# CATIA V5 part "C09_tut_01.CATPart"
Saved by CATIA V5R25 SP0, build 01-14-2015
Part number: Part1
Bounding box of the stored display mesh (mm): x -75 to 140, y -40 to 40, z 0 to 100
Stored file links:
  E:\ashutosh\Academics\Catia\CATIA V5-6R2013_partfiles\Tutorials_ver_2\C09_tut_01.CATPart
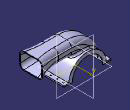
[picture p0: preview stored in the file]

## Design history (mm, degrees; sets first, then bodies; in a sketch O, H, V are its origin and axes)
Body1 (main body)
  Sketch1 on zx-plane, origin (0, 0, 0), H (-1, 0, 0), V (0, 0, 1)
    arc A1 centre (0, 0) radius 60 from (60, 0) to (-60, 0) ccw
    line L1 (-60, 0) -> (60, 0)
    point P1 (-60, 0)
    radius A1 = 60
    coincidence: P1 H
    horizontal: L1 H
  Pad1: profile Sketch1, direction (0, 1, 0), length 40, mirrored extent
  Sketch2 on zx-plane, origin (0, 0, 0), H (-1, 0, 0), V (0, 0, 1)
    point P1 (-82, 100)
    line L1 (-82, 100) -> (-40, 100)
    arc A1 centre (-40, 0) radius 100 from (-40, 100) to (60, 0) cw
    point P4 (60, 0)
    reference projected line E1 (-60, 0) -> (60, 0) from edge [face of Pad1 from Sketch1.L1 | end face of Pad1]
    reference projected point E2 (60, 0) from edge [face of Pad1 from Sketch1.A1 | face of Pad1 from Sketch1.L1]
    reference projected arc E3 centre (0, 0) radius 60 from (60, 0) to (-60, 0) ccw from edge [face of Pad1 from Sketch1.A1 | end face of Pad1]
    distance P1 E1 = 100
    distance P1 V = 82
    horizontal: L1 H
    tangency: A1 L1, A1 E3
    coincidence: P4 E2
  Plane1: type Normal, Curve Sketch2, RefPoint Sketch2.P1, Ratio 0
  Sketch3 on Plane1, origin (82, 0, 0), H (0, 1, 0), V (0, 0, 1)
    line L1 (-29, 100) -> (29, 100)
    line L2 (29, 100) -> (29, 58)
    line L3 (29, 58) -> (-29, 58)
    line L4 (-29, 58) -> (-29, 100)
    reference projected point E1 (0, 100) from Sketch2.P1
    distance L4 V = 29
    length L1 = 58
    length L2 = 42
    horizontal: L1 H, L3 H
    vertical: L2 V, L4 V
    coincidence: L1 E1
  Rib1: profile Sketch3, centre curve Sketch2
  Plane2: type Offset, RefPlane face of Rib1, Offset 58, reversed
  Sketch4 on Plane2, origin (140, 0, 0), H (0, -1, 0), V (0, 0, 1)
    line L1 (36.53, 100) -> (-36.47, 100)
    line L2 (-36.47, 100) -> (-36.47, 47)
    line L3 (-36.47, 47) -> (36.53, 47)
    line L4 (36.53, 47) -> (36.53, 100)
    reference projected line E1 (40, 0) -> (-40, 0) from edge [face of Rib1 | face of Pad1 from Sketch1.A1]
    distance L4 V = 36.53
    distance L1 E1 = 100
    length L2 = 53
    length L1 = 73
    horizontal: L1 H, L3 H
    vertical: L2 V, L4 V
  Loft1: solid, Sections ({boundary Boundary {extract ExtractElem face of Rib1}}; Sketch4), StartFace face of Rib1
  Fillet1: radius 15, on edge [face of Rib1 | face of Rib1] (x3); edge [face of Loft1 | face of Loft1]
  Shell1: ExtOffset 0, Face (face of Rib1; face of Loft1), IntOffset 2.5
  Fillet2: radius 5, on edge [face of Pad1 from Sketch1.A1 | face of Fillet1]
  Sketch5 on end face of Pad1, origin (0, 40, 0), H (-1, 0, 0), V (0, 0, 1)
    arc A1 centre (0, 0) radius 49 from (49, 0) to (-49, 0) ccw
    line L1 (-49, 0) -> (49, 0)
    point P1 (-49, 0)
    radius A1 = 49
    coincidence: P1 H
    horizontal: L1 H
  Pocket1: profile Sketch5, direction (0, -1, 0), through (limit type 6)
  Sketch6 on start face of Pad1, origin (0, -40, 0), H (1, 0, 0), V (0, 0, 1)
    circle A1 centre (0, 0) radius 15
    radius A1 = 15
  Pocket2: profile Sketch6, direction (0, 1, 0), through (limit type 6)
  Sketch7 on end face of Pad1, origin (0, 40, 0), H (-1, 0, 0), V (0, 0, 1)
    line L1 (60, 0) -> (75, 0)
    line L2 (75, 0) -> (75, 4)
    line L3 (75, 4) -> (59.8665, 4)
    point P4 (59.8665, 4)
    reference projected line E1 (-60, 0) -> (60, 0) from edge [face of Rib1 | end face of Pad1]
    reference intersected line E2 (60, 0) -> (-60, 0) from face of Rib1
    reference projected arc E3 centre (0, 0) radius 60 from (60, 0) to (-60, 0) ccw from edge [face of Pad1 from Sketch1.A1 | end face of Pad1]
    projected arc E4 centre (0, 0) radius 60 from (60, 0) to (-60, 0) ccw from edge [face of Pad1 from Sketch1.A1 | end face of Pad1]
    projected arc E5 centre (0, 0) radius 60 from (60, 0) to (59.8665, 4) ccw from edge [face of Pad1 from Sketch1.A1 | end face of Pad1]
    length L2 = 4
    distance L2 V = 75
    horizontal: L1 H, L3 H
    vertical: L2 V
    coincidence: L1 E1, L1 E2, P4 E3
  Pad2: profile Sketch7, direction (0, -1, 0), length 80
  Mirror1: of Pad2, about yz-plane
  Sketch8 on face of Mirror1, origin (0, 0, 4), H (1, 0, 0), V (0, 1, 0)
    point P1 (-67, 30)
    reference projected line E1 (-75, 40) -> (-59.8665, 40) from edge [face of Pad2 from Sketch7.L3 | face of Mirror1]
    reference projected line E2 (-75, 40) -> (-75, -40) from edge [face of Pad2 from Sketch7.L2 | face of Pad2 from Sketch7.L3]
    point P2 (67, 30)
    distance E1 P1 = 10
    distance P1 E2 = 8
    symmetry: P1 P2 V
  Sketch9 on face of Pad2 from Sketch7.L3, origin (-67, 30, 4), H (1, 0, 0), V (0, 1, 0)
    point P1 (0, 0)
    reference projected point E1 (0, 0) from Sketch8.P1
    coincidence: E1 P1
  Hole1: placed by Sketch9, at (-67, 30, 4) direction (0, 0, -1), diameter 4, through (limit type 6)
  RectPattern1: of Hole1, direction 1 instances 4, spacing 20, along edge [face of Pad2 from Sketch7.L2 | face of Pad2 from Sketch7.L3]
  Sketch10 on face of Mirror1, origin (67, 30, 4), H (1, 0, 0), V (0, 1, 0)
    point P1 (0, 0)
    reference projected point E1 (0, 0) from Sketch8.P2
    coincidence: E1 P1
  Hole2: placed by Sketch10, at (67, 30, 4) direction (0, 0, -1), diameter 4, through (limit type 6)
  RectPattern2: of Hole2, direction 1 instances 4, spacing 20, along edge [face of Mirror1 | face of Mirror1]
